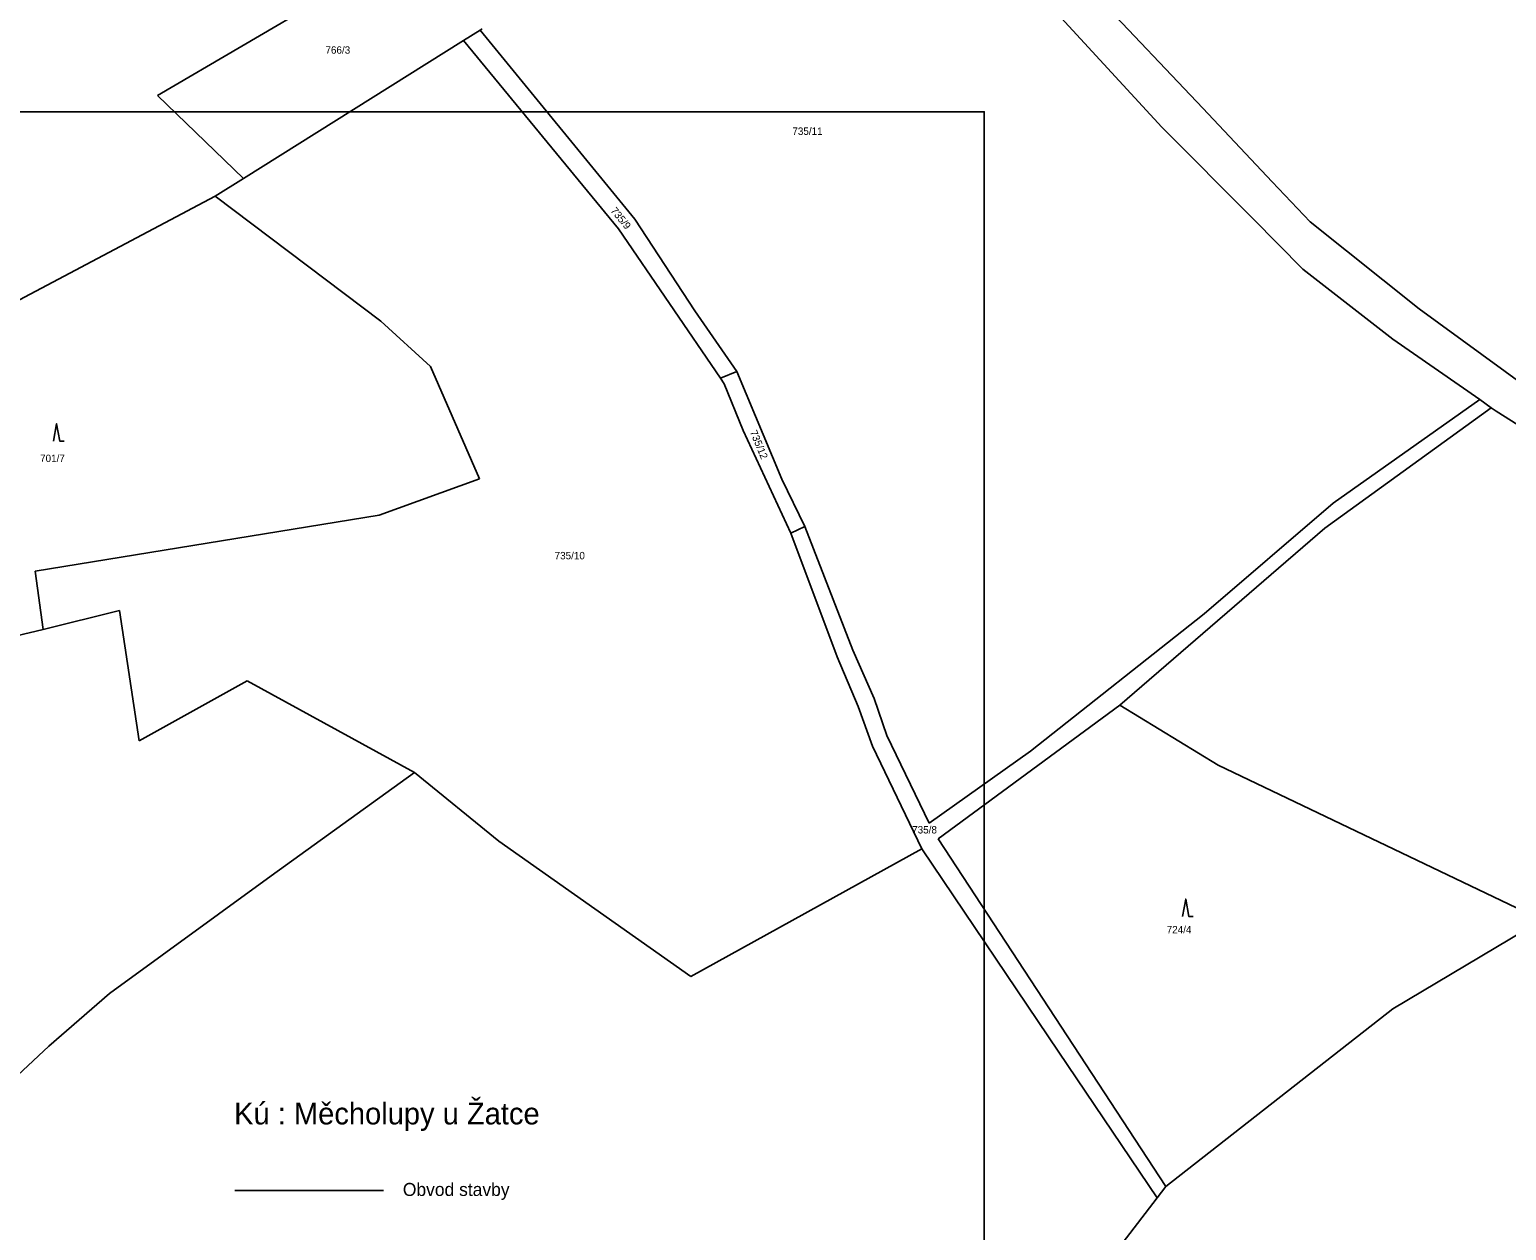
# Model space of a CAD drawing. Extents: x -801907 to -800293, y -1016964 to -1015684.
# Drawn here: x -800931.6 to -800592.1, y -1016580.7 to -1016304.7 of the extents above; entities that cross this region are included whole.
import ezdxf

# ---------------------------------------------------------------- set-up
doc = ezdxf.new("R2010")
doc.units = 0
for name, color, linetype in [('Default', 7, 'Continuous'), ('KN_HRANICE', 7, 'Continuous'), ('KN_KULTURY', 7, 'Continuous'), ('KN_PARCELY', 7, 'Continuous'), ('LEGENDA', 7, 'Continuous')]:
    doc.layers.add(name, color=color, linetype=linetype)

# ---------------------------------------------------------------- blocks, each defined once
blk = doc.blocks.new('308')
at = {"layer": 'Default'}
blk.add_lwpolyline([(-0.75, 0), (0, 4), (0.75, 0), (1.75, 0)], dxfattribs=at)

msp = doc.modelspace()

# ---------------------------------------------------------------- linework, layer by layer
at = {"layer": 'KN_HRANICE'}
for p, q in [((-800902.15, -1016319.78), (-800832.94, -1016279.31)), ((-800693.94, -1016288.84), (-800661.88, -1016322.76)), ((-800701.43, -1016294.3), (-800671.28, -1016327.06)), ((-800828.01, -1016304.81), (-800831.82, -1016307.2)), ((-800827.51, -1016304.5), (-800828.01, -1016304.81)), ((-800828.01, -1016304.81), (-800792.42, -1016348.23)), ((-800831.82, -1016307.2), (-800882.39, -1016338.89)), ((-800796.15, -1016350.5), (-800831.82, -1016307.2)), ((-800882.39, -1016338.89), (-800902.15, -1016319.78)), ((-800661.88, -1016322.76), (-800645.93, -1016339.64)), ((-800671.28, -1016327.06), (-800650.33, -1016348.18)), ((-800882.39, -1016338.89), (-800888.88, -1016342.96)), ((-800645.93, -1016339.64), (-800637.22, -1016348.86)), ((-800888.88, -1016342.96), (-800989.55, -1016396.29)), ((-800888.88, -1016342.96), (-800850.85, -1016371.7)), ((-800792.42, -1016348.23), (-800778.66, -1016369.34)), ((-800650.33, -1016348.18), (-800638.85, -1016359.75)), ((-800637.22, -1016348.86), (-800612.1, -1016368.85)), ((-800772.77, -1016384.8), (-800796.15, -1016350.5)), ((-800638.85, -1016359.75), (-800618.15, -1016375.86)), ((-800778.66, -1016369.34), (-800769.02, -1016383.23)), ((-800612.1, -1016368.85), (-800587.87, -1016386.56)), ((-800850.85, -1016371.7), (-800839.44, -1016382.12)), ((-800618.15, -1016375.86), (-800598.22, -1016389.73)), ((-800839.44, -1016382.12), (-800828.17, -1016407.96)), ((-800772.77, -1016384.8), (-800769.02, -1016383.23)), ((-800769.02, -1016383.23), (-800758.65, -1016408.03)), ((-800771.89, -1016386.09), (-800772.77, -1016384.8)), ((-800767.55, -1016396.86), (-800771.89, -1016386.09)), ((-800631.89, -1016413.56), (-800598.22, -1016389.73)), ((-800598.22, -1016389.73), (-800595.57, -1016391.58)), ((-800633.84, -1016419.29), (-800595.57, -1016391.58)), ((-800595.57, -1016391.58), (-800594.45, -1016392.36)), ((-800594.45, -1016392.36), (-800517.53, -1016440.89)), ((-800756.61, -1016420.44), (-800767.55, -1016396.86)), ((-800828.17, -1016407.96), (-800851.17, -1016416.29)), ((-800758.65, -1016408.03), (-800753.36, -1016418.9)), ((-800661.55, -1016438.97), (-800631.89, -1016413.56)), ((-800851.17, -1016416.29), (-800930.26, -1016429.17)), ((-800753.36, -1016418.9), (-800756.61, -1016420.44)), ((-800745.94, -1016448.84), (-800756.61, -1016420.44)), ((-800753.36, -1016418.9), (-800742.32, -1016447.29)), ((-800680.93, -1016459.96), (-800633.84, -1016419.29)), ((-800930.26, -1016429.17), (-800928.47, -1016442.57)), ((-800928.47, -1016442.57), (-800910.92, -1016438.2)), ((-800910.92, -1016438.2), (-800906.36, -1016468.13)), ((-800701.47, -1016470.52), (-800661.55, -1016438.97)), ((-800987.67, -1016456.78), (-800928.47, -1016442.57)), ((-800742.32, -1016447.29), (-800737.41, -1016458.44)), ((-800741.13, -1016460.27), (-800745.94, -1016448.84)), ((-800906.36, -1016468.13), (-800881.56, -1016454.34)), ((-800881.56, -1016454.34), (-800843.12, -1016475.44)), ((-800737.82, -1016469.42), (-800741.13, -1016460.27)), ((-800737.41, -1016458.44), (-800734.48, -1016466.94)), ((-800722.74, -1016490.67), (-800680.93, -1016459.96)), ((-800680.93, -1016459.96), (-800658.32, -1016473.75)), ((-800734.48, -1016466.94), (-800724.77, -1016487.12)), ((-800726.49, -1016492.96), (-800737.82, -1016469.42)), ((-800724.77, -1016487.12), (-800701.47, -1016470.52)), ((-800658.32, -1016473.75), (-800583.94, -1016509.31)), ((-800876, -1016499.2), (-800843.12, -1016475.44)), ((-800843.12, -1016475.44), (-800823.71, -1016491.19)), ((-800823.71, -1016491.19), (-800779.57, -1016522.34)), ((-800670.38, -1016570.61), (-800722.74, -1016490.67)), ((-800779.57, -1016522.34), (-800726.49, -1016492.96)), ((-800726.49, -1016492.96), (-800694.98, -1016539.69)), ((-800913.21, -1016526.21), (-800876, -1016499.2)), ((-800583.94, -1016509.31), (-800618.21, -1016529.77)), ((-800927.12, -1016538.33), (-800913.21, -1016526.21)), ((-800618.21, -1016529.77), (-800670.38, -1016570.61)), ((-800944.95, -1016554.98), (-800927.12, -1016538.33)), ((-800694.98, -1016539.69), (-800672.38, -1016573.21)), ((-800672.38, -1016573.21), (-800702.65, -1016612.58)), ((-800670.38, -1016570.61), (-800672.38, -1016573.21))]:
    msp.add_line(p, q, dxfattribs=at)
at = {"layer": 'LEGENDA'}
msp.add_line((-800884.41, -1016571.52), (-800850.21, -1016571.52), dxfattribs=at)
msp.add_lwpolyline([(-801306.12, -1016323.56), (-800712.12, -1016323.56), (-800712.12, -1016743.56), (-801306.12, -1016743.56)], close=True, dxfattribs=at)

# ---------------------------------------------------------------- block references
at = {"layer": 'KN_KULTURY'}
for p in [(-800925.34, -1016399.28), (-800665.8, -1016508.54)]:
    msp.add_blockref('308', p, dxfattribs=at)

# ---------------------------------------------------------------- texts
at = {"layer": 'KN_PARCELY'}
for s, p in [('766/3', (-800863.55, -1016310.21)), ('735/11', (-800756.22, -1016328.87)), ('701/7', (-800929.15, -1016404.07)), ('735/10', (-800810.87, -1016426.43)), ('735/8', (-800728.68, -1016489.45)), ('724/4', (-800670.17, -1016512.41))]:
    msp.add_text(s, height=1.7, dxfattribs=at).set_placement(p)
for s, rotation, p in [('735/9', 309.283, (-800798.1, -1016346.35)), ('735/12', 292.438, (-800766.01, -1016397.16))]:
    msp.add_text(s, height=1.7, rotation=rotation, dxfattribs=at).set_placement(p)
at = {"layer": 'LEGENDA'}
for s, height, p in [('Kú : Měcholupy u Žatce', 5, (-800884.55, -1016556.33)), ('Obvod stavby', 3, (-800845.76, -1016572.78))]:
    msp.add_text(s, height=height, dxfattribs=at).set_placement(p)

doc.saveas('drawing.dxf')
